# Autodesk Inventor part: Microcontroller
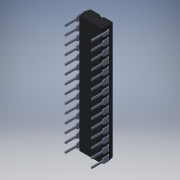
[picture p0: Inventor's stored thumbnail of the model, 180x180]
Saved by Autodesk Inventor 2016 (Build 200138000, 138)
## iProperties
Created: 2018-03
Part Number: Microcontroller
Material: Générique
Document SubType Name: Modeling
Designer: Bruno
Density: 1 g/cm^3
Appearance: Par défaut
Author: Bruno
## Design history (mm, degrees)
feature "Composite1"
body "Srf1"
